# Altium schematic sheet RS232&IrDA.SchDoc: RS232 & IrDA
size A4; DocumentNumber: MB1165; Revision: C.1; SheetNumber: 10; SheetTotal: 17; Project: STM32469I-EVAL
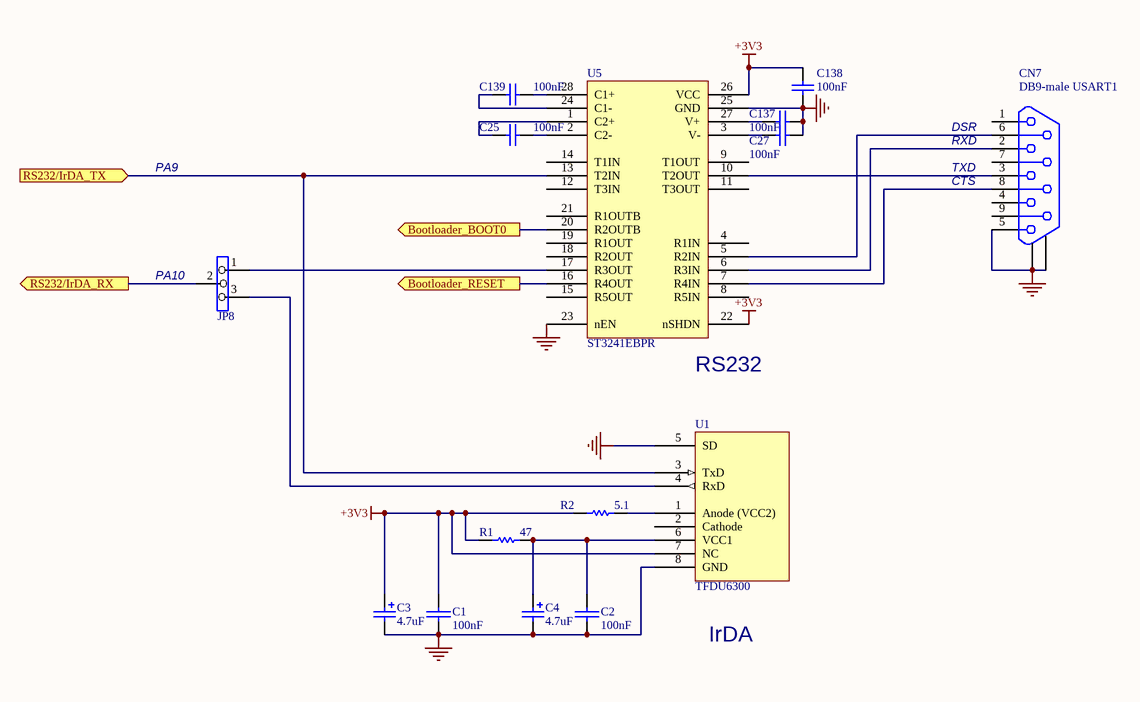
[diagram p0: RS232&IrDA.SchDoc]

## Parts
C1  100nF  [0603C]
C2  100nF  [0603C]
C3  4.7uF  [TAN-A]
C4  4.7uF  [TAN-A]
C25  100nF  [0603C]
C27  100nF  [0603C]
C137  100nF  [0603C]
C138  100nF  [0603C]
C139  100nF  [0603C]
CN7  DB9-male USART1  [DB9/M]
JP8  (no value)  [SIP3]
R1  47  [0603R]
R2  5.1  [0603R]
U1  TFDU6300  [IR_VISHAY3]
U5  ST3241EBPR  [SSOP28_0R65_10R2X7R8]

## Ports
Bootloader_BOOT0 (out), Bootloader_RESET (out), RS232/IrDA_RX (out), RS232/IrDA_TX (in)

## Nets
+3V3: C1.1 C3.1 C138.1 R1.1 R2.1 U1.7(NC) U5.22(nSHDN) U5.26(VCC)
GND: C1.2 C2.2 C3.2 C4.2 C27.1 C137.1 C138.2 CN7.5 CN7.10 CN7.11 U1.5(SD) U1.8(GND) U5.23(nEN) U5.25(GND)
Bootloader_BOOT0: U5.20(R2OUTB) ; port Bootloader_BOOT0
Bootloader_RESET: U5.16(R4OUT) ; port Bootloader_RESET
RS232/IrDA_RX: JP8.2 ; port RS232/IrDA_RX
RS232/IrDA_TX: U1.3(TxD) U5.13(T2IN) ; port RS232/IrDA_TX
NetC2_1: C2.1 C4.1 R1.2 U1.6(VCC1)
NetC25_1: C25.1 U5.1(C2+)
NetC25_2: C25.2 U5.2(C2-)
NetC27_2: C27.2 U5.3(V-)
NetC137_2: C137.2 U5.27(V+)
NetC139_1: C139.1 U5.24(C1-)
NetC139_2: C139.2 U5.28(C1+)
NetCN7_2: CN7.2 U5.6(R3IN)
NetCN7_3: CN7.3 U5.10(T2OUT)
NetCN7_6: CN7.6 U5.5(R2IN)
NetCN7_8: CN7.8 U5.7(R4IN)
NetJP8_1: JP8.1 U5.17(R3OUT)
NetJP8_3: JP8.3 U1.4(RxD)
NetR2_2: R2.2 U1.1(Anode_(VCC2))

Not connected (* = marked no-connect by the designer): CN7 1 4 7 9; U1 2(Cathode); U5 4(R1IN) 8(R5IN) 9(T1OUT) 11(T3OUT) 12(T3IN) 14(T1IN) 15(R5OUT) 18(R2OUT) 19(R1OUT) 21(R1OUTB)

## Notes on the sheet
- PA9
- (near CN7) RXD
- (near CN7) TXD
- (near CN7) DSR
- (near CN7) CTS
- (near JP8) PA10
- (near U5) RS232
- IrDA

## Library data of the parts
C1 C2 = CAP: Capacitor
C3 C4 = Cap Pol1: Polarized Capacitor (Radial); Value: 100pF
C25 C27 C137-C139 = Cap: Capacitor; Value: 10nF
CN7 = DB9-USART
JP8 = Jumper3
R1 R2 = Res1: Resistor; Value: 1K
U1 = TFDU4300
U5 = ST3241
